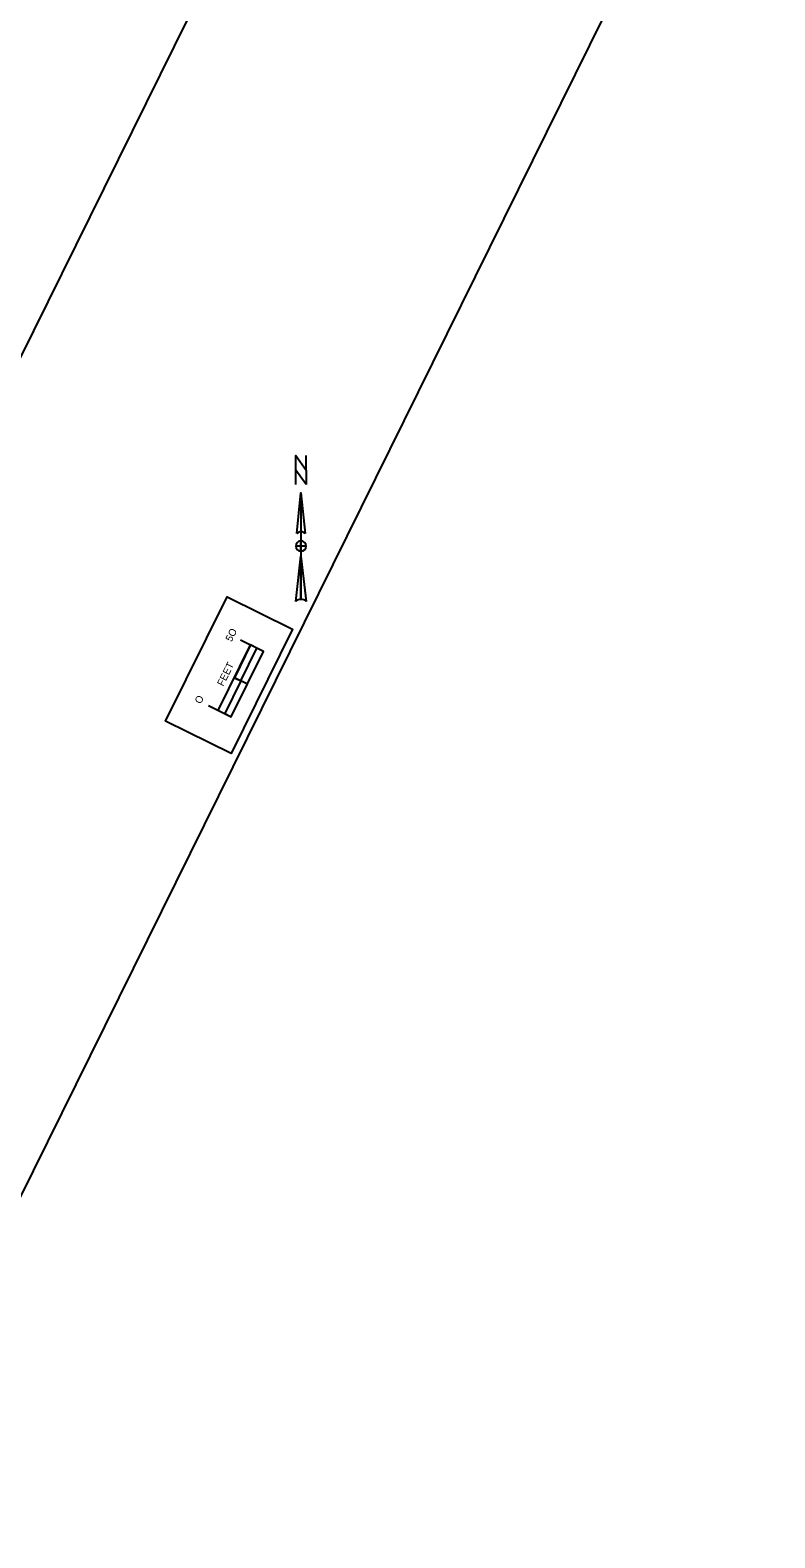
# Model space of a CAD drawing. Extents: x 14104283 to 14120882, y 8635219 to 8671666.
# Drawn here: x 14120371 to 14120882, y 8669937 to 8670971 of the extents above; entities that cross this region are included whole.
import ezdxf

# ---------------------------------------------------------------- set-up
doc = ezdxf.new("R2010")
doc.units = 0
for name, color, linetype in [('dsnCellsNorthArrow', 7, 'Continuous'), ('dsnCellsScaleBlock', 7, 'Continuous'), ('dsnNonPlotable', 7, 'Continuous')]:
    doc.layers.add(name, color=color, linetype=linetype)

msp = doc.modelspace()

# ---------------------------------------------------------------- linework, layer by layer
at = {"layer": 'dsnCellsNorthArrow'}
for p, q in [((14120557.2, 8670653.9), (14120560, 8670625.8)), ((14120557.2, 8670653.9), (14120557.2, 8670580.7)), ((14120554.4, 8670625.8), (14120554.4, 8670625.8)), ((14120554.5, 8670626), (14120555, 8670626.6)), ((14120557.2, 8670613.8), (14120557.2, 8670613.8)), ((14120553.7, 8670579.3), (14120557.2, 8670610.3))]:
    msp.add_line(p, q, dxfattribs=at)
msp.add_lwpolyline([(14120560.7, 8670659.6), (14120553.7, 8670669.4), (14120553.7, 8670679.3), (14120560.7, 8670669.4)], close=True, dxfattribs=at)
for points in [[(14120553.7, 8670659.6), (14120553.7, 8670679.3), (14120560.7, 8670669.4), (14120560.7, 8670679.3)], [(14120554.4, 8670625.8), (14120557.2, 8670653.9), (14120557.2, 8670627.2)], [(14120557.2, 8670613.8), (14120557.2, 8670617.3), (14120553.7, 8670617.3)], [(14120560.7, 8670617.3), (14120557.2, 8670617.3), (14120557.2, 8670620.8)], [(14120557.2, 8670580.7), (14120557.2, 8670610.3), (14120560.7, 8670579.3)]]:
    msp.add_lwpolyline(points, dxfattribs=at)
for centre, radius, start, end in [((14120557.2, 8670623.7), 3.52, 90.0204, 143.1257), ((14120557.2, 8670623.7), 3.52, 36.8481, 90.0218), ((14120557.2, 8670617.3), 3.52, 90, 180), ((14120557.2, 8670617.3), 3.52, 180, 270), ((14120557.2, 8670617.3), 3.52, 0, 90), ((14120557.2, 8670617.3), 3.52, 270, 360), ((14120557.2, 8670575.6), 5.1, 89.9894, 133.619), ((14120557.2, 8670575.6), 5.11, 46.4021, 90.0006)]:
    msp.add_arc(centre, radius, start, end, dxfattribs=at)
at = {"layer": 'dsnCellsScaleBlock'}
msp.add_line((14120520.5, 8670522.6), (14120511.5, 8670527), dxfattribs=at)
msp.add_line((14120520.5, 8670522.6), (14120511.5, 8670527), dxfattribs=at)
for points in [[(14120464.4, 8670497.3), (14120506.5, 8670582.5), (14120551.4, 8670560.3), (14120509.3, 8670475.2)], [(14120509.3, 8670475.2), (14120464.4, 8670497.3), (14120506.5, 8670582.5), (14120551.4, 8670560.3)], [(14120515.9, 8670524.8), (14120527, 8670547.3), (14120522.6, 8670549.5), (14120511.5, 8670527)], [(14120509.4, 8670500.2), (14120520.5, 8670522.6), (14120515.9, 8670524.8), (14120504.9, 8670502.4)]]:
    msp.add_lwpolyline(points, close=True, dxfattribs=at)
for points in [[(14120493.7, 8670508), (14120509.4, 8670500.2), (14120531.5, 8670545), (14120515.8, 8670552.8)], [(14120500.4, 8670504.6), (14120522.6, 8670549.5)]]:
    msp.add_lwpolyline(points, dxfattribs=at)
at = {"layer": 'dsnNonPlotable'}
for points in [[(14119282, 8670260.6), (14119976.8, 8671665.7), (14120882.2, 8671218.1), (14120187.4, 8669813)], [(14119506.2, 8670149.8), (14120200.9, 8671554.9), (14120653.6, 8671331.1), (14119958.8, 8669926)]]:
    msp.add_lwpolyline(points, close=True, dxfattribs=at)

# ---------------------------------------------------------------- texts
at = {"layer": 'dsnCellsScaleBlock'}
for s, p in [('5O', (14120509.6, 8670551.3)), ('FEET', (14120503.9, 8670520.8)), ('O', (14120488.5, 8670508.7))]:
    msp.add_text(s, height=5, rotation=63.6912, dxfattribs=at).set_placement(p)

doc.saveas('drawing.dxf')
